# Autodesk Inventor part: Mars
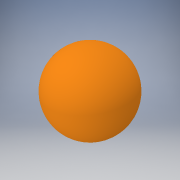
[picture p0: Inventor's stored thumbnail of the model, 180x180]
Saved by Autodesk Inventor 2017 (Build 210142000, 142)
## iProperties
Created: 2016-07
Part Number: Mars
Material: Generic
Document SubType Name: Modeling
Designer: Stan
Density: 1 g/cm^3
Appearance: Orange
Author: Stan
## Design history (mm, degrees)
sketch "Sketch1"
  geometry: L1 (-3.175, -8.98)-(0, -8.98); L2 (0, 9.525)-(0, -8.98); A1 r 9.525 centre (0, 0) between (0, 9.525) and (-3.175, -8.98); 1 further point
  constraints: 4 end point, 2 point on circle, 1 centre point, 1 coincident, 1 horizontal, 1 perpendicular
  dimensions: "d0" = 19.05 diameter of A1; "d2" = 3.175 distance from line of L1.start L2; "d3" = 0 distance from line of point (0, 0) L2
revolve "Revolution1" sketch "Sketch1" stored, may be unused: angle "d4" = 90 deg
sketch "Sketch2"
  geometry: C1 r 1.587 at (0, 0); 1 further point
  constraints: 1 centre point, 1 coincident
  dimensions: "d5" = 3.175 diameter of C1
extrude "Extrusion1" cut sketch "Sketch2" distance "d6" = 6.35; taper "d7" = 0 deg
body "Solid1"
